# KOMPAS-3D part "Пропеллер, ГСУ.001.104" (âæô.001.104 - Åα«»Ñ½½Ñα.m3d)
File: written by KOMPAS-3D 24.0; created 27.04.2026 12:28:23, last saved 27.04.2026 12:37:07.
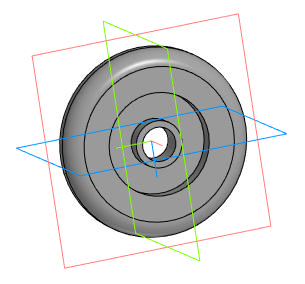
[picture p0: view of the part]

Document properties: Автор: User7; Полное имя файла: C:\Users\User7\Desktop\Двигатель мясорубки\ГСУ.001.104 - Пропеллер.m3d

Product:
- Part/product: Пропеллер  | designation ГСУ.001.104
    Масса: 0.033692

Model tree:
1. Эскиз:1
2. Элемент выдавливания:1
     Расстояние 1 = 6
3. Скругление:1  (with: Ребро.Элемент выдавливания:1)
     Радиус = 4
4. Эскиз:2  (with: Грань.Элемент выдавливания:1)
5. Элемент выдавливания:2  (with: Грань.Элемент выдавливания:1)
     Расстояние 2 = 4; Смещение 2 = 2
6. Скругление:2  (with: Ребро.Элемент выдавливания:2)
     Радиус = 4
7. Эскиз:3  (with: Грань.Элемент выдавливания:2)
8. Элемент выдавливания:3  (with: Грань.Элемент выдавливания:1)
     Расстояние 1 = 4
9. Эскиз:4  (with: Грань.Элемент выдавливания:1)
10. Элемент выдавливания:4  (with: Грань.Элемент выдавливания:3)
     Расстояние 2 = 4; Смещение 2 = 2
11. Фаска:1  (with: Ребро.Элемент выдавливания:3)
     Угол = 35; Длина 1 = 2; Длина 2 = 1.40042
12. Эскиз:5  (with: Грань.Элемент выдавливания:1, Ребро.Элемент выдавливания:2, Ребро.Элемент выдавливания:3)
13. Элемент выдавливания:5  (with: Грань.Элемент выдавливания:2)
     Расстояние 1 = -4
14. Массив по концентрической сетке:1  (with: Элемент выдавливания:5, Эскиз:5, Грань.Элемент выдавливания:3)  (8 pattern instances)
     Шаг 2 = 360
15. Эскиз:6  (with: Грань.Элемент выдавливания:1)
16. Элемент выдавливания:6

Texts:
  ГСУ.001.104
